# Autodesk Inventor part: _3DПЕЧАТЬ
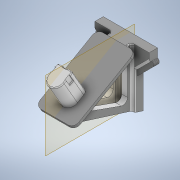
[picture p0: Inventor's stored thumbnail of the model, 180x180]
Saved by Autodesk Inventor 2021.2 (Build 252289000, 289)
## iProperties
Created: 2025-12
Part Number: _3DПЕЧАТЬ
Material: Типовые
Document SubType Name: Modeling
Designer: BR
Density: 1 g/cm^3
Appearance: По умолчанию
Author: BR
Part Number: link_60
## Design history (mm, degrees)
derived "подбор угла.iam"
node "РабПлоскость1"
sketch "Эскиз1"
  geometry: L1 (16.01, 97.643)-(106.14, 45.607) reference; L2 (16.01, 97.643)-(0, 106.887); L3 (0, 107.233)-(0, 92.233) reference; L4 (16.01, 97.643)-(34.497, 97.643); L5 (0, 67.478)-(0, 0) reference; L6 (0, 106.887)-(0, 0); L7 (106.14, 45.607)-(114.8, 40.607) reference; L8 (0, 0)-(114.8, 40.607); L9 (114.8, 40.607)-(16.01, 97.643); 3 further points
  constraints: 10 end point, 2 collinear, 1 equal length, 1 horizontal, 1 point on line
  dimensions: "d1" = 150 deg angle of L4 L2
extrude "Выдавливание1" join sketch "Эскиз1" stored distance "d2" = 35; taper "d3" = 0 deg
sketch "Эскиз2"
  geometry: L1 (7.35, 102.643)-(114.8, 40.607) reference; L2 (0, 0)-(114.8, 40.607) reference; L3 (0, 0)-(0, 107.233) reference; L4 (7.35, 102.643)-(0, 106.887); L5 (0, 107.233)-(0, 0) reference; L6 (-3.881, 9.234)-(91.006, 42.798); L7 (91.006, 42.798)-(2.35, 93.983); L8 (2.35, 93.983)-(-5, 98.227); L9 (-5.215, 13.005)-(81.488, 43.674); L10 (0.35, 90.519)-(-7, 94.763); L11 (81.488, 43.674)-(87.684, 45.866); 4 further points
  constraints: 14 end point, 1 point on line, 2 other
  dimensions: "d4" = 10 distance between parallel lines of L1 L7; "d5" = 4 distance between parallel lines of L6 L9
extrude "Выдавливание2" cut sketch "Эскиз2" stored distance "d6" = 105.5; taper "d7" = 0 deg
sketch "Эскиз3"
  geometry: L1 (0, 67.478)-(0, 0) reference; L2 (0, 12.366)-(8, 12.366); L3 (8, 12.366)-(8, 97.366); L4 (8, 97.366)-(0, 97.366); L5 (0, 97.366)-(0, 12.366); 2 further points
  constraints: 8 end point, 2 parallel, 1 horizontal, 1 perpendicular, 1 point on line
  dimensions: "d8" = 8 distance of L4.end L3.end; "d9" = 85 distance of L3.end L2.end
extrude "Выдавливание3" join sketch "Эскиз3" stored distance "d10" = 35; taper "d11" = 0 deg
sketch "Эскиз4"
  geometry: L1 (0, 0)-(0, 107.233) reference; L2 (0, 0)-(114.8, 40.607) reference; L3 (7.35, 102.643)-(114.8, 40.607) reference; L4 (10, 107.233)-(7.35, 102.643) reference; L5 (0, 107.233)-(10, 107.233) reference; L6 (8, 17.68)-(8, 90.721) reference; L7 (8, 90.721)-(86.449, 45.429) reference; L8 (86.449, 45.429)-(8, 17.68) reference; L9 (7.35, 102.643)-(0, 102.643); L10 (0, 107.233)-(0, 92.233) reference; 2 further points
  constraints: 2 end point, 1 perpendicular, 1 point on line
extrude "Выдавливание4" cut sketch "Эскиз4" stored distance "d12" = 15; taper "d13" = 0 deg
fillet "Сопряжение1" dims "d14" = 2
fillet "Сопряжение3" dims "d16" = 8
fillet "Сопряжение4" dims "d17" = 5
fillet "Сопряжение5" dims "d18" = 4.25
fillet "Сопряжение6" dims "d19" = 2
mirror "Зеркальное отражение1"
fillet "Сопряжение7" dims "d20" = 2.5
sketch "Эскиз5"
  geometry: L1 (25, -4.5)-(24.474, -7.976) reference; L2 (14.986, -17.541)-(11.5, -18) reference; L3 (25, -4.5)-(25, 8); L4 (25, 8)-(24.905, 9.595) reference; L5 (23.934, 13.127)-(24.157, 12.696) reference; L6 (24.093, 12.672)-(24.623, 11.167) reference; L7 (15.5, 14)-(22.282, 14) reference; L8 (23.216, 13.768)-(23.385, 13.626) reference; L9 (15.5, 14)-(7.5, 14) reference; L10 (15.5, 14)-(11.5, 14); L11 (11.5, 14)-(11.5, -18); A1 r 13.513 centre (11.487, -4.487) between (-2.025, -4.5) and (25, -4.5); A2 r 13.5 centre (11.5, 8) between (25, 8) and (24.157, 12.696); A3 r 2 centre (22.282, 12) between (24.157, 12.696) and (22.282, 14); 4 further points
  constraints: 9 point on circle, 6 end point, 3 centre point, 1 midpoint, 1 perpendicular, 1 tangent, 1 vertical
extrude "Выдавливание5" cut sketch "Эскиз5" distance "d21" = 47.897; taper "d22" = 0 deg
sketch "Эскиз6"
  geometry: L1 (45.15, -24.923)-(45.15, 79.15) reference; L2 (35.15, 89.15)-(30.137, 89.15) reference; L3 (30.137, 89.15)-(-3.975, 89.15) reference; L4 (-3.975, 89.15)-(-12.1, 89.15) reference; L5 (-22.1, 79.15)-(-22.1, -24.923) reference; L6 (-12.1, -34.923)-(35.15, -34.923) reference; L7 (22.283, 14)-(22.282, 14) reference; L8 (22.763, 13.941)-(22.283, 14) reference; L9 (22.764, 13.941)-(22.763, 13.941) reference; L10 (23.216, 13.768)-(22.764, 13.941) reference; L11 (23.615, 13.491)-(23.216, 13.768) reference; L12 (23.615, 13.49)-(23.615, 13.491) reference; L13 (23.934, 13.127)-(23.615, 13.49) reference; L14 (23.935, 13.126)-(23.934, 13.127) reference; L15 (24.157, 12.696)-(23.935, 13.126) reference; L16 (24.158, 12.692)-(24.157, 12.696) reference; L17 (24.623, 11.167)-(24.158, 12.692) reference; L18 (24.905, 9.598)-(24.623, 11.167) reference; L19 (24.905, 9.595)-(24.905, 9.598) reference; L20 (24.906, 9.59)-(24.905, 9.595) reference; L21 (25, 8)-(24.906, 9.59) reference; L22 (25, -4.5)-(25, 8) reference; L23 (24.999, -4.508)-(25, -4.5) reference; L24 (24.54, -7.994)-(24.999, -4.508) reference; L25 (24.537, -8.001)-(24.54, -7.994) reference; L26 (23.191, -11.25)-(24.537, -8.001) reference; L27 (23.187, -11.256)-(23.191, -11.25) reference; L28 (21.046, -14.046)-(23.187, -11.256) reference; L29 (21.04, -14.051)-(21.046, -14.046) reference; L30 (18.25, -16.191)-(21.04, -14.051) reference; L31 (18.243, -16.194)-(18.25, -16.191) reference; L32 (14.994, -17.54)-(18.243, -16.194) reference; L33 (14.986, -17.541)-(14.994, -17.54) reference; L34 (11.5, -18)-(14.986, -17.541) reference; L35 (11.492, -17.999)-(11.5, -18) reference; L36 (8.006, -17.54)-(11.492, -17.999) reference; L37 (7.999, -17.537)-(8.006, -17.54) reference; L38 (4.75, -16.191)-(7.999, -17.537) reference; L39 (4.744, -16.187)-(4.75, -16.191) reference; L40 (1.954, -14.046)-(4.744, -16.187) reference; L41 (1.949, -14.04)-(1.954, -14.046) reference; L42 (-0.191, -11.25)-(1.949, -14.04) reference; L43 (-0.194, -11.243)-(-0.191, -11.25) reference; L44 (-1.54, -7.994)-(-0.194, -11.243) reference; L45 (-1.541, -7.986)-(-1.54, -7.994) reference; L46 (-2, -4.5)-(-1.541, -7.986) reference; L47 (-2, 8)-(-2, -4.5) reference; L48 (-1.906, 9.59)-(-2, 8) reference; L49 (-1.905, 9.595)-(-1.906, 9.59) reference; L50 (-1.624, 11.164)-(-1.905, 9.595) reference; L51 (-1.623, 11.167)-(-1.624, 11.164) reference; L52 (-1.622, 11.171)-(-1.623, 11.167) reference; L53 (-1.157, 12.696)-(-1.622, 11.171) reference; L54 (-1.157, 12.697)-(-1.157, 12.696) reference; L55 (-0.934, 13.127)-(-1.157, 12.697) reference; L56 (-0.934, 13.127)-(-0.934, 13.127) reference; L57 (-0.615, 13.491)-(-0.934, 13.127) reference; L58 (-0.217, 13.768)-(-0.615, 13.491) reference; L59 (-0.216, 13.769)-(-0.217, 13.768) reference; L60 (0.237, 13.941)-(-0.216, 13.769) reference; L61 (0.238, 13.941)-(0.237, 13.941) reference; L62 (0.718, 14)-(0.238, 13.941) reference; L63 (0.737, 14)-(0.718, 14) reference; L64 (22.263, 14)-(0.737, 14) reference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; A1 r 10 centre (35.15, 79.15) between (45.15, 79.15) and (35.15, 89.15) reference; A2 r 10 centre (-12.1, 79.15) between (-12.1, 89.15) and (-22.1, 79.15) reference; A3 r 10 centre (-12.1, -24.923) between (-22.1, -24.923) and (-12.1, -34.923) reference; A4 r 10 centre (35.15, -24.923) between (35.15, -34.923) and (45.15, -24.923) reference; 1 further point
extrude "Выдавливание6" cut sketch "Эскиз6" distance "d23" = 49; taper "d24" = 0 deg
sketch "Эскиз7"
  geometry: L1 (37.1, 30.422)-(37.1, 42.922) reference; L2 (27.6, 48.922)-(19.6, 48.922) reference; L3 (27.6, 48.922)-(34.382, 48.922) reference; L4 (10.1, 34.922)-(12.1, 34.922) reference; L5 (12.1, 42.922)-(12.1, 34.922) reference; L6 (10.1, 42.922)-(12.1, 42.922) reference; L7 (19.6, 46.922)-(19.6, 48.922) reference; L8 (23.6, 46.922)-(19.6, 46.922) reference; L9 (23.6, 46.922)-(23.6, 48.922) reference; L10 (23.6, 48.922)-(23.6, 16.922); L11 (37.1, 34.922)-(35.1, 34.922); L12 (35.1, 42.922)-(35.1, 34.922); L13 (37.1, 42.922)-(35.1, 42.922); L14 (27.6, 46.922)-(27.6, 48.922); L15 (23.6, 46.922)-(27.6, 46.922); A1 r 13.513 centre (23.587, 30.435) between (10.075, 30.422) and (37.1, 30.422) reference; A2 r 13.5 centre (23.6, 42.923) between (37.1, 42.922) and (36.257, 47.618) reference; A3 r 2 centre (34.382, 46.923) between (36.257, 47.618) and (34.382, 48.922) reference; 5 further points
  constraints: 12 end point, 6 symmetric about line, 1 vertical
extrude "Выдавливание7" join sketch "Эскиз7" distance "d25" = 47.9; taper "d27" = 0 deg; dims "d26" = 1.7, "d28" = 0
mirror "Зеркальное отражение2"
sketch "Эскиз8"
  geometry: L1 (23, 0)-(25, 0) reference; L2 (25, 8)-(25, 0) reference; L3 (25, 8)-(23, 8) reference; L4 (23, 8)-(23, 0) reference; L5 (-2, 0)-(0, 0) reference; L6 (0, 0)-(0, 8) reference; L7 (0, 8)-(-2, 8) reference; L8 (-2, 0)-(-2, 8) reference; L9 (7.5, 12)-(15.5, 12) reference; L10 (15.5, 12)-(15.5, 14) reference; L11 (7.5, 14)-(15.5, 14) reference; L12 (7.5, 14)-(7.5, 12) reference; 1 further point
extrude "Выдавливание8" join sketch "Эскиз8" distance "d29" = 36; taper "d30" = 0 deg
mirror "Зеркальное отражение3"
fillet "Сопряжение8" dims "d31" = 1.5
node "РабПлоскость2"
sketch "Эскиз9"
  geometry: L1 (-110.55, 39.104)-(-101.89, 44.104) reference; L2 (6.661, -1.503)-(18.75, -1.503) reference; L3 (-110.55, 39.104)-(18.75, -1.503); L4 (18.75, -1.503)-(5.888, -27.682); L5 (5.888, -27.682)-(-122.883, 30.223); L6 (-122.883, 30.223)-(-110.55, 39.104); 1 further point
  constraints: 8 end point
extrude "Выдавливание9" cut sketch "Эскиз9" extent not by distance; stored distance "d32" = 0; taper "d33" = 0 deg
node "Твердое тело1"
node "Ryobi_link_30_base1.1.ipt:1" dims "d0" = 10
node "Ryobi_link_30_base2.ipt:1" dims "d0" = 10
node "Спроецированная петля1"
node "Спроецированная петля2"
node "Спроецированная петля3"
node "Спроецированная петля4"
node "Спроецированная петля5"
node "Спроецированная петля6"
node "Спроецированная петля7"
